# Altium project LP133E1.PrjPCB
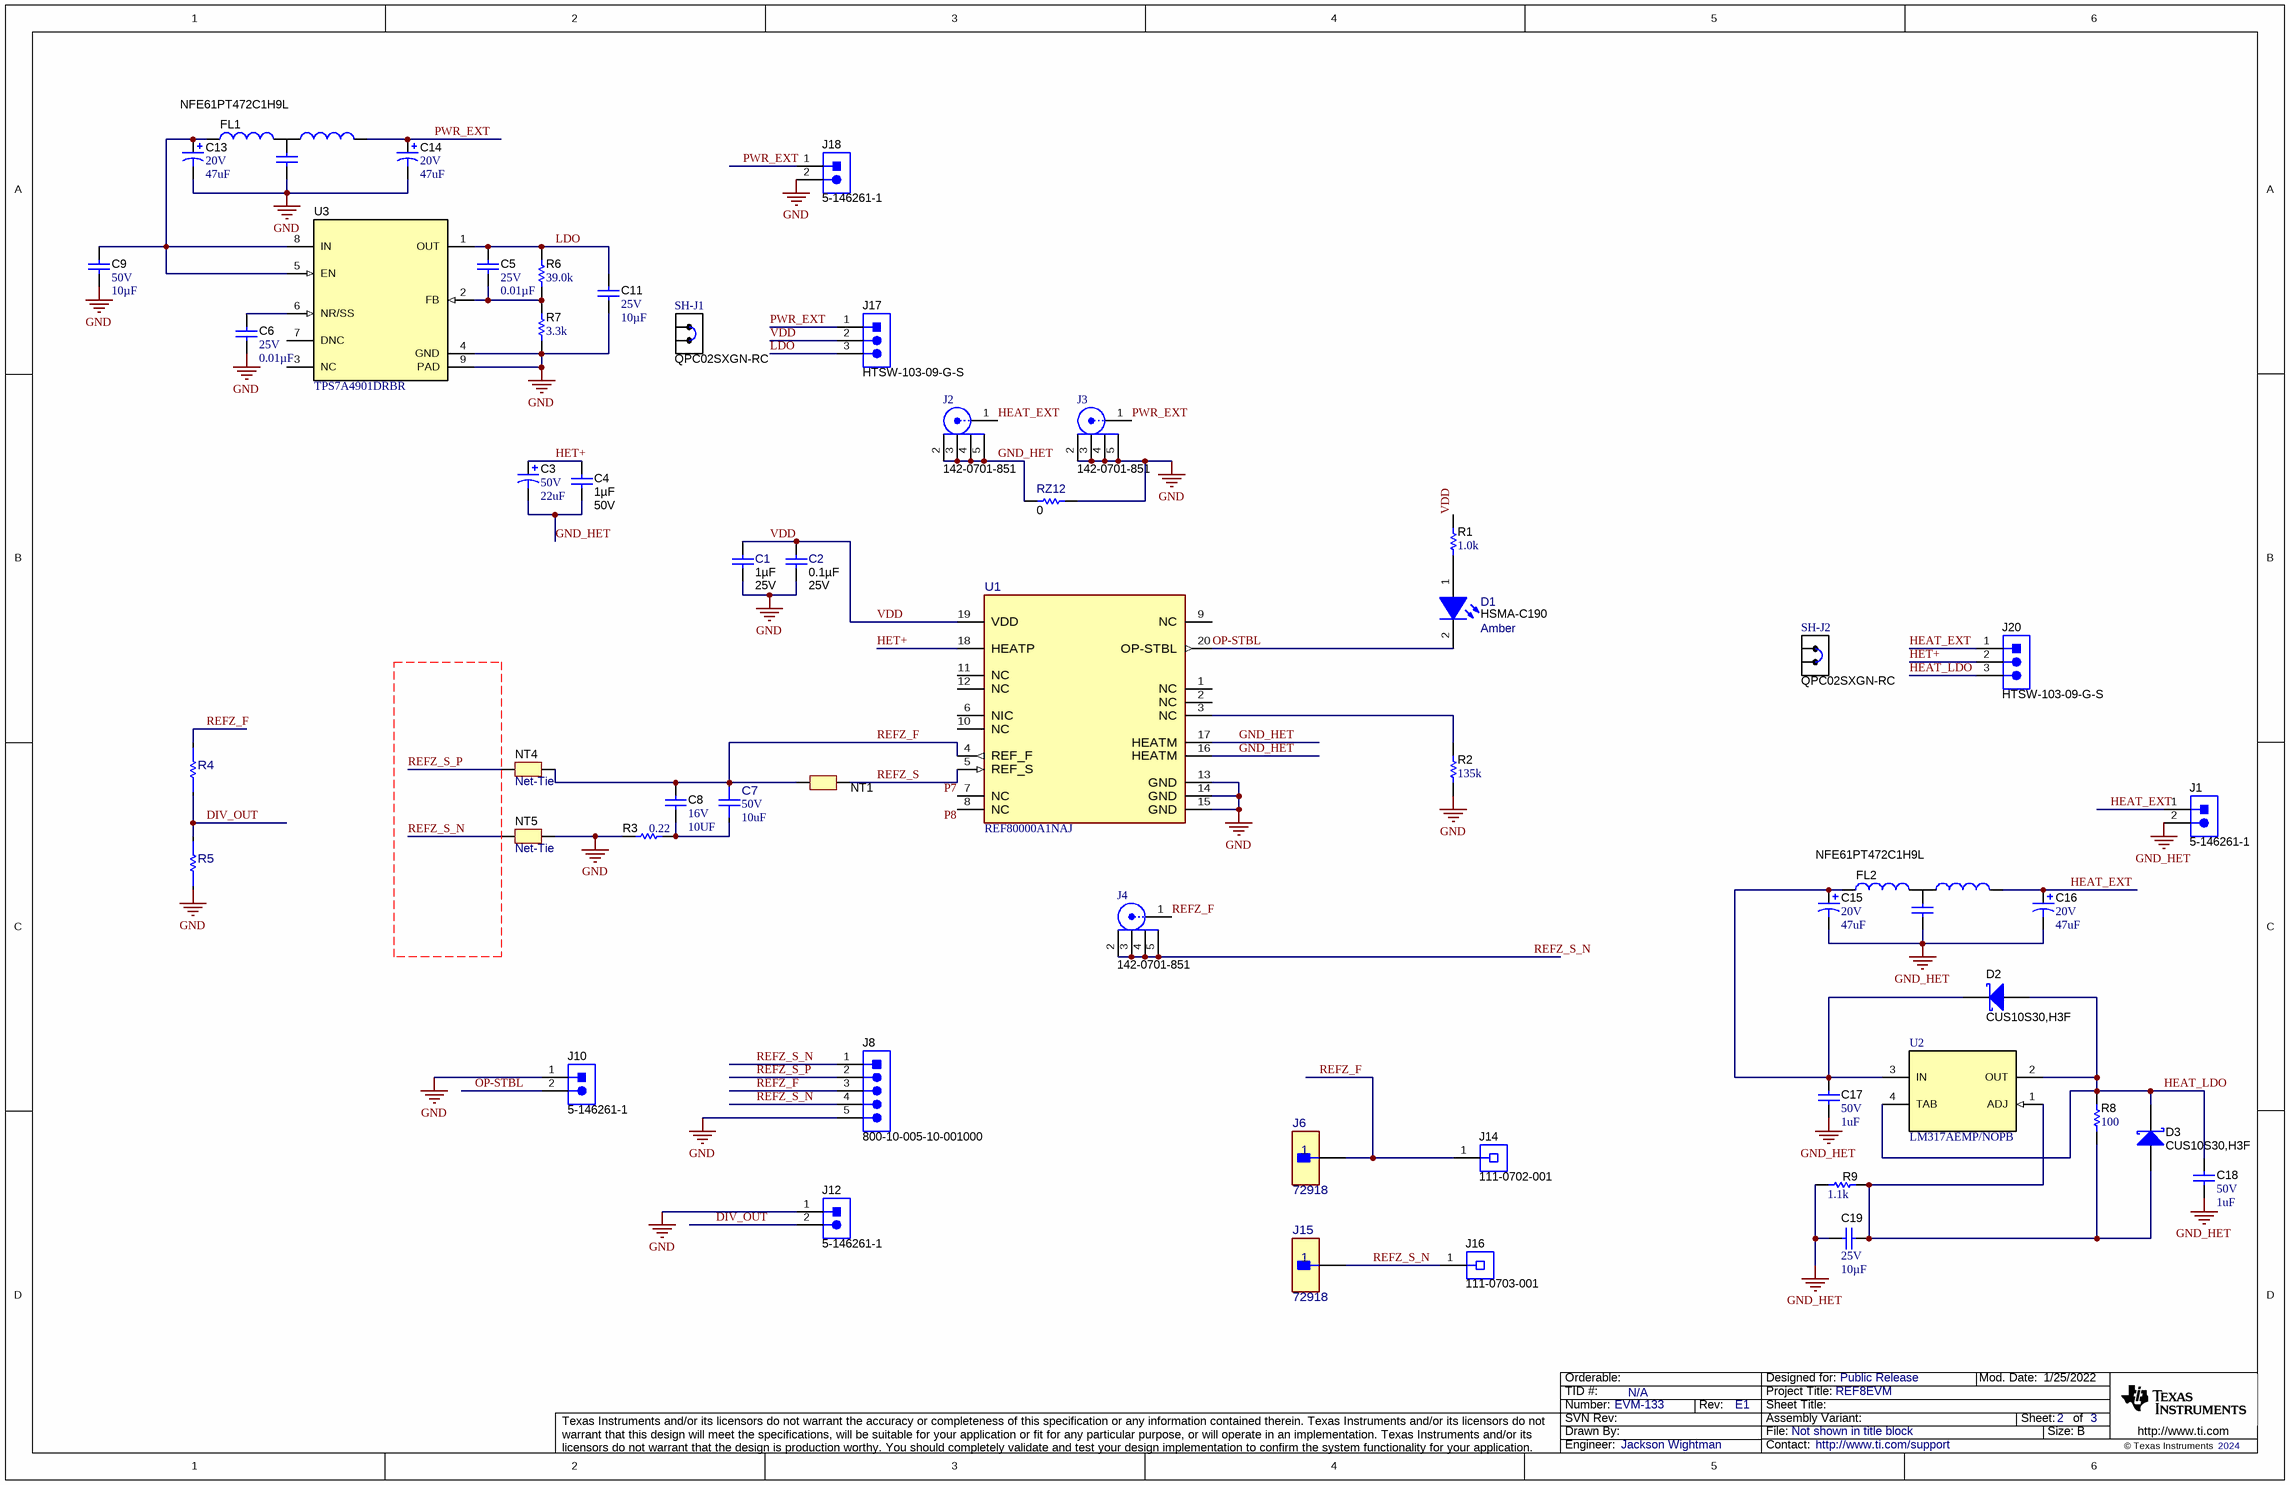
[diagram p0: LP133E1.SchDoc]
CopyrightYear: 2024; PCB_Layout: Jackson Wightman; PCB_Rev: E1; PRJ_Customer: Public Release; PRJ_Engineer: Jackson Wightman; PRJ_Number: EVM-133; PRJ_Title: REF8EVM; SCH_Rev: E1; TechSupport: http://www.ti.com/support; TID: N/A
2 sheets, 74 parts. Net scope: global (net labels, ports and power ports of the same name join across sheets).
Board file: LP133E1.PcbDoc
Sheets:
  LP133E1.SchDoc
  LP133E1_Hardware.SchDoc

## Sheet LP133E1.SchDoc
size 431 x 279 mm; Date: Not shown in title block; ApprovedBy: Not shown in title block; CheckedBy: Not shown in title block; Author: Not shown in title block; CompanyName: Not shown in title block; Engineer: Not shown in title block; Organization: Not shown in title block; Address1: Not shown in title block; Address2: Not shown in title block; Address3: Not shown in title block; Address4: Not shown in title block; DocumentNumber: 2; Revision: Use project parameter SCH_Rev; SheetNumber: 2; SheetTotal: 3; PageSetup: Record=PageOptions¦CenterHorizontal=True¦CenterVertical=True¦PrintScale=1.00¦XCorrection=1.00¦YCorrection=1.00¦PrintKind=0¦BorderSize=5000000¦LeftOffset=0¦BottomOffset=0¦Orientation=2¦PaperLength=1000¦PaperWidth=1000¦Scale=100¦PaperSource=15¦PrintQuality=600¦MediaType=1¦DitherType=10¦PaperKind=Letter¦PrintScaleMode=1

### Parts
C1  Cap_F: 1µF  VDC_V: 25V  [0603]  (hidden comment: GRJ188R71E105KE11D)
C2  ValueDisplayed: 0.1µF  VDC_V: 25V  [0603]  (hidden comment: CL10A104KA8NNNC)
C3  VDC_V: 50V  ValueDisplayed: 22uF  [7361-38]  (hidden comment: TAJV226K050RNJ)
C4  Cap_F: 1µF  VDC_V: 50V  [0805_HV]  (hidden comment: CL21B105KBFNFNE)
C5  VDC_V: 25V  ValueDisplayed: 0.01µF  [0603]  (hidden comment: C0603C103F3GACTU)
C6  VDC_V: 25V  ValueDisplayed: 0.01µF  [0603]  (hidden comment: C0603C103F3GACTU)
C7  VDC_V: 50V  ValueDisplayed: 10uF  [FP-MKS2B051001N00JSSD_RADIAL-MFG]  (hidden comment: MKS2B051001N00JSSD)
C8  VDC_V: 16V  ValueDisplayed: 10UF  [1812]  (hidden comment: 16MU106MC44532)
C9  VDC_V: 50V  ValueDisplayed: 10µF  [1210_270]  (hidden comment: CL32B106KBJNNWE)
C11  VDC_V: 25V  ValueDisplayed: 10µF  [0603]  (hidden comment: GRM188R61E106KA73D)
C13  VDC_V: 20V  ValueDisplayed: 47uF  [7343-20]  (hidden comment: 20TQC47MYF)
C14  VDC_V: 20V  ValueDisplayed: 47uF  [7343-20]  (hidden comment: 20TQC47MYF)
C15  VDC_V: 20V  ValueDisplayed: 47uF  [7343-20]  (hidden comment: 20TQC47MYF)
C16  VDC_V: 20V  ValueDisplayed: 47uF  [7343-20]  (hidden comment: 20TQC47MYF)
C17  VDC_V: 50V  ValueDisplayed: 1uF  [0805_HV]  (hidden comment: C2012X6S1H105K125AB)
C18  VDC_V: 50V  ValueDisplayed: 1uF  [0805_HV]  (hidden comment: C2012X6S1H105K125AB)
C19  VDC_V: 25V  ValueDisplayed: 10µF  [0603]  (hidden comment: GRM188R61E106KA73D)
D1  HSMA-C190  value Amber  [HSMx-C190_Amber]
D2  CUS10S30,H3F  [SOD-323]
D3  CUS10S30,H3F  [SOD-323]
FL1  NFE61PT472C1H9L  [2706]
FL2  NFE61PT472C1H9L  [2706]
J1  5-146261-1  [CONN_5-146261-1]
J2  142-0701-851  [Emerson_142-0701-851]
J3  142-0701-851  [Emerson_142-0701-851]
J4  142-0701-851  [Emerson_142-0701-851]
J6  72918  [FP-72918_CONNECTOR_BANANA_PLUG-MFG]
J8  800-10-005-10-001000  [Mill-Max_800-10-005-10-001000]
J10  5-146261-1  [CONN_5-146261-1]
J12  5-146261-1  [CONN_5-146261-1]
J14  111-0702-001  [Emerson_111-0702-001]
J15  72918  [FP-72918_CONNECTOR_BANANA_PLUG-MFG]
J16  111-0703-001  [Emerson_111-0703-001]
J17  HTSW-103-09-G-S  [Samtec_HTSW-103-09-x-S]
J18  5-146261-1  [CONN_5-146261-1]
J20  HTSW-103-09-G-S  [Samtec_HTSW-103-09-x-S]
NT1  Net-Tie  [Net-Tie_10mil]  (value not drawn)  (net tie, no BOM)
NT4  Net-Tie  [Net-Tie_10mil]  (net tie, no BOM)
NT5  Net-Tie  [Net-Tie_10mil]  (net tie, no BOM)
R1  ValueDisplayed: 1.0k  [0402]  (hidden comment: CRCW04021K00JNED)
R2  ValueDisplayed: 135k  [0603]  (hidden comment: RT0603DRE07135KL)
R3  ValueDisplayed: 0.22  [0603]  (hidden comment: ERJ-3RQFR22V)
R4  Y0062100K000T9L  [FP-Y0062100K000T9L_RADIAL-MFG]  (value not drawn)
R5  Y0062100K000T9L  [FP-Y0062100K000T9L_RADIAL-MFG]  (value not drawn)
R6  ValueDisplayed: 39.0k  [0603]  (hidden comment: RC0603FR-0739KL)
R7  ValueDisplayed: 3.3k  [0603]  (hidden comment: RC0603JR-073K3L)
R8  ValueDisplayed: 100  [1206]  (hidden comment: CRCW1206100RFKEA)
R9  ValueDisplayed: 1.1k  [1206]  (hidden comment: CRCW12061K10JNEA)
RZ12  ValueDisplayed: 0  [0805_HV]  (hidden comment: CRCW08050000Z0EA)
SH-J1  QPC02SXGN-RC  [FP-QPC02SXGN-RC_JUMPER-MFG]
SH-J2  QPC02SXGN-RC  [FP-QPC02SXGN-RC_JUMPER-MFG]
U1  REF80000A1NAJ  [NAJ0020A-IPC_C]
U2  LM317AEMP/NOPB  [DCY0004A_N]
U3  TPS7A4901DRBR  [DRB0008A]

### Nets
GND: C1.2 C2.2 C6.2 C9.2 C11.2 C13.2(-) C14.2(-) FL1.2 J3.2 J3.3 J3.4 J3.5 J8.5 J10.1 J12.1 J18.2 NT5.1 R2.1 R3.1 R5.1 R7.1 RZ12.1 U1.13(GND) U1.14(GND) U1.15(GND) U3.4(GND) U3.9(PAD)
GND_HET: C3.2(-) C4.2 C15.2(-) C16.2(-) C17.2 C18.2 C19.1 FL2.2 J1.2 J2.2 J2.3 J2.4 J2.5 R9.1 RZ12.2 U1.16(HEATM) U1.17(HEATM)
DIV_OUT: J12.2 R4.1 R5.2
HEAT_EXT: C16.1(+) FL2.3 J1.1 J2.1 J20.1
HEAT_LDO: C18.1 D2.2(A) D3.1(K) J20.3 R8.2 U2.2(OUT) U2.4(TAB)
HET+: C3.1(+) C4.1 J20.2 U1.18(HEATP)
LDO: C5.1 C11.1 J17.3 R6.2 U3.1(OUT)
OP-STBL: D1.2(K) J10.2 U1.20(OP-STBL)
PWR_EXT: C14.1(+) FL1.3 J3.1 J17.1 J18.1
REFZ_F: C7.1 C8.1 J4.1 J6.1 J8.3 J14.1 NT1.1 NT4.1 R4.2 U1.4(REF_F)
REFZ_S: NT1.2 U1.5(REF_S)
REFZ_S_N: J4.2 J4.3 J4.4 J4.5 J8.1 J8.4 J15.1 J16.1 NT5.2
REFZ_S_P: J8.2 NT4.2
VDD: C1.1 C2.1 J17.2 R1.2 U1.19(VDD)
NetC5_2: C5.2 R6.1 R7.2 U3.2(FB)
NetC6_1: C6.1 U3.6(NR/SS)
NetC7_2: C7.2 C8.2 R3.2
NetC9_1: C9.1 C13.1(+) FL1.1 U3.5(EN) U3.8(IN)
NetC15_1: C15.1(+) C17.1 D2.1(K) FL2.1 U2.3(IN)
NetC19_2: C19.2 D3.2(A) R8.1 R9.2 U2.1(ADJ)
NetD1_1: D1.1(A) R1.1
NetR2_2: R2.2 U1.3(NC)

Not connected (* = marked no-connect by the designer): U1 1(NC) 2(NC) 6(NIC) 7(NC) 8(NC) 9(NC) 10(NC) 11(NC) 12(NC); U3 3(NC) 7(DNC)

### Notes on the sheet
- Labels drawn without touching a wire or pin: P7, P8

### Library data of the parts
C1 = CMP-0079720-1: CAP, CERM, 1 µF, 25 V,+/- 10%, X7R, 0603; Manufacturer: MuRata; TaMin_C: -55°C; Polarized: N; SizeAreaWB_mm2: 4.68; U/M: EA; Value: 1uF; TaMax_C: 125°C; SizeZ_mm: 1; SizeX_mm: 1.6; SizeY_mm: 0.8; SizeArea_mm2: 1.28; AEC Category: Q200
C2 = CMP-0085577-2: CAP, CERM, 0.1 µF, 25 V,+/- 10%, X5R, 0603; Manufacturer: Samsung Electro-Mechanics; SizeZ_mm: 1; AEC Qualified: N; SizeY_mm: 0.8; Green_REACh: Incomplete; SizeArea_mm2: 1.28; Green_Lifecycle: Active; SizeX_mm: 1.6; AEC Category: Q200; TaMin_C: -55°C; SizeAreaWB_mm2: 4.68; Cap_F: 100nF; U/M: EA; TaMax_C: 85°C; Value: 0.1uF
C3 = CMP-0064995-1: CAP, TA, 22 uF, 50 V, +/- 10%, 0.6 ohm, SMD; Manufacturer: AVX; TaMin_C: -55°C; ESR_ohm: 0.6; Polarized: Y; Green_Lifecycle: Active; SizeAreaWB_mm2: 75.33; Green_REACh: Passed; Value1: 0.6 ohm; U/M: EA; Value: 22uF; TaMax_C: 125°C; SizeZ_mm: 3.8; SizeX_mm: 7.3; SizeY_mm: 6.1; SizeArea_mm2: 44.53; CompType: Capacitor; AEC Qualified: N; Cap_F: 22µF; IRMS_A: 645mA; AEC Category: Q200
C4 = CMP-0080611-1: CAP, CERM, 1 µF, 50 V,+/- 10%, X7R, 0805; Manufacturer: Samsung; TaMin_C: -55°C; Polarized: N; SizeAreaWB_mm2: 6.75; U/M: EA; Value: 1uF; TaMax_C: 125°C; SizeZ_mm: 1.45; SizeX_mm: 2; SizeY_mm: 1.25; Cap_Case: 0805; SizeArea_mm2: 2.5; AEC Category: Q200
C5 C6 = CMP-0079995-1: CAP, CERM, 0.01 µF, 25 V,+/- 1%, C0G/NP0, 0603; Manufacturer: Kemet; TaMin_C: -55°C; Polarized: N; Green_Lifecycle: Active; SizeAreaWB_mm2: 4.68; Green_REACh: Passed; U/M: EA; Value: 0.01uF; TaMax_C: 125°C; SizeZ_mm: 1; SizeX_mm: 1.6; SizeY_mm: 0.8; SizeArea_mm2: 1.28; Cap_F: 10nF; AEC Category: Q200
C7 = CMP-0096040-1: 10 µF Film Capacitor 30V 50V Polyester, Polyethylene Terephthalate (PET), Metallized Radial; Manufacturer: WIMA; SizeZ_mm: 16mm; AEC Grade: Grade 2; AEC Qualified: Yes; Tolerance_%: 5%; Cap_F: 10µF; Value: 10µF
C8 = CMP-0012475-2: CAP FILM 10UF 20% 16VDC 1812; Manufacturer: Rubycon; TaMin_C: -40°C; Polarized: N; SizeAreaWB_mm2: 14.7; Value1: Unknown; U/M: EA; TaMax_C: 85°C; SizeZ_mm: 1.35; SizeX_mm: 3.2; SizeY_mm: 2.5; SizeArea_mm2: 8; Cap_F: 10µF; AEC Category: Q200
C9 = CMP-0079201-1: CAP, CERM, 10 µF, 50 V,+/- 10%, X7R, 1210; Manufacturer: Samsung Electro-Mechanics; TaMin_C: -55°C; ESR_ohm: 5m; Polarized: N; SizeAreaWB_mm2: 14.7; Value1: 0.005 ohm; U/M: EA; Value: 10uF; TaMax_C: 125°C; SizeZ_mm: 2.7; SizeX_mm: 3.2; SizeY_mm: 2.5; Cap_Case: 1210; SizeArea_mm2: 8; AEC Category: Q200
C11 C19 = CMP-0860569-1: CAP, CERM, 10 µF, 25 V,+/- 10%, X5R, 0603; Manufacturer: MuRata; SizeZ_mm: 1; AEC Category: Q200; AEC Qualified: N; TaMin_C: -55°C; SizeY_mm: 0.8; SizeAreaWB_mm2: 4.68; SizeArea_mm2: 1.28; TaMax_C: 85°C; SizeX_mm: 1.6; Value: 10uF; U/M: EA
C13-C16 = CMP-0012618-4: CAP, Tantalum Polymer, 47 uF, 20 V, +/- 20%, 0.055 ohm, 7343-20 SMD; Manufacturer: Panasonic; TaMin_C: -55°C; ESR_ohm: 55m; Polarized: Y; SizeAreaWB_mm2: 58.59; Value: 47uF; TaMax_C: 105°C; SizeZ_mm: 2; SizeX_mm: 7.3; SizeY_mm: 4.3; SizeArea_mm2: 31.39; CompType: Capacitor; AEC Qualified: N; Cap_F: 47µF; IRMS_A: 1.45A; AEC Category: Q200
C17 C18 = CMP-0007855-1: CAP, CERM, 1 uF, 50 V, +/- 10%, X6S, 0805; Manufacturer: TDK; TaMin_C: -55°C; ESR_ohm: 8.782m; Polarized: N; SizeAreaWB_mm2: 6.75; Value1: 0.008782 ohm; U/M: EA; Value: 1uF; TaMax_C: 105°C; SizeZ_mm: 1.45; SizeX_mm: 2; SizeY_mm: 1.25; Cap_Case: 0805; SizeArea_mm2: 2.5; Cap_F: 1µF; IRMS_A: 2.2049A; AEC Category: Q200
D1 = CMP-0003041-3: LED, Amber, SMD; Manufacturer: Avago; SizeY_mm: 0.8; Vf_V: 1.9V; Value1: 0.06W; Ir_A: 100µA; Power_TotalModule: 60mW; SizeZ_mm: 0.9; SizeX_mm: 1.6; Tjmax_C: 95°C; SizeArea_mm2: 1.28; Vr_V: 5V; SizeAreaWB_mm2: 4.68; Angle: 170; Io_A: 20mA; Type: AlInGaP
D2 D3 = CMP-0028893-2: Diode, Schottky, 20 V, 1 A, SOD-323; Manufacturer: Toshiba; Io_A: 1A; AEC Qualified: N; SizeY_mm: 1.35; SizeAreaWB_mm2: 8.695; Green_REACh: Incomplete; Value2: 0.37V; Vf_V: 370mV; TJmax_C: 125°C; Green_Lifecycle: Not Set; SizeZ_mm: 1; SizeArea_mm2: 3.645; Vr_V: 20V; AEC Category: Q101; SizeX_mm: 2.7; Value: 20V
FL1 FL2 = CMP-0001717-2: Filter LC High freq 4700PF, 2706; Manufacturer: MuRata
J1 J10 J12 J18 = CMP-0054947-1: Header, 100mil, 2x1, Gold, TH; Manufacturer: TE Connectivity; CT: FALSE; Green_REACh: Passed; CNHeader: TRUE; Green_Lifecycle: Active
J2-J4 = CMP-0055822-3: Connector, End launch SMA, 50 ohm, SMT; Manufacturer: Cinch Connectivity; Green_Lifecycle: Not Set; Green_REACh: Incomplete
J6 J15 = CMP-0092456-1: Banana Plug Connector Standard Banana Threaded, External (Nut) -; Manufacturer: Pomona Electronics; Current_A: 36A; AEC Qualified: No; ContactFinish: Nickel
J8 = CMP-0055088-1: Header, 100mil, 5x1, TH; Manufacturer: Mill-Max; CT: FALSE; CNHeader: TRUE
J14 = CMP-0075036-1: Binding Post, Red, TH; Manufacturer: Cinch Connectivity; CT: False; CompType: Receptacle
J16 = CMP-0075035-1: Binding Post, Black, TH; Manufacturer: Cinch Connectivity; CT: False
J17 J20 = CMP-0075627-1: Header, 100mil, 3x1, Gold, TH; Manufacturer: Samtec; Pitch_mm: 2.54; Gender: Male; Cert_CSA: Y; CT: False; Row_Count: 1
NT1 NT4 NT5 = CMP-0078142-3: Single point connection between nets.
R1 = CMP-0026852-2: RES, 1.0 k, 5%, 0.063 W, 0402; Manufacturer: Vishay-Dale; Power_W: 63mW; TempCo: 200 ppm/C; Value_Code: 1k00; U/M: EA; Value: 1.0k; EIA_Code: E24; Res_ohm: 1k; SizeX_mm: 1; SizeY_mm: 0.5; SizeZ_mm: 0.6; Value2: 0.063W; VDC_V: 50V; AEC Category: Q200
R2 = CMP-0024657-2: RES, 135 k, 0.5%, 0.1 W, 0603; Manufacturer: Yageo America; Power_W: 100mW; TempCo: 50 ppm/C; U/M: EA; Value: 135k; EIA_Code: E192; SizeX_mm: 1.6; SizeY_mm: 0.8; SizeZ_mm: 1; Value2: 0.1W; SizeArea_mm2: 1.28; VDC_V: 75V; AEC Category: Q200
R3 = CMP-0022712-3: RES, 0.22, 1%, 0.1 W, AEC-Q200 Grade 0, 0603; Manufacturer: Panasonic; Power_W: 100mW; TempCo: 300 ppm/C; Value_Code: R220; Value: 0.22; EIA_Code: E96; SizeX_mm: 1.6; SizeY_mm: 0.8; SizeZ_mm: 1; Value2: 0.1W; SizeArea_mm2: 1.28; AEC Qualified: Y; AEC Category: Q200; AEC Grade: 0; SizeAreaWB_mm2: 4.68
R4 R5 = CMP-0096565-1: Res Metal Foil 100K Ohm 0.01% 3/5W ±1ppm/°C Molded RDL Thru-Hole Bulk; Manufacturer: Vishay Precision Group; Power_W: 600mW; Standoff Height: 0.254mm; AEC Qualified: No; SizeZ_mm: 8.53mm; VDC_V: 300V
R6 = CMP-0023073-5: RES, 39.0 k, 1%, 0.1 W, 0603; Manufacturer: Yageo; Power_W: 100mW; TempCo: 100 ppm/C; Value_Code: 39k0; Value: 39.0k; Res_ohm: 39k; SizeX_mm: 1.6; SizeY_mm: 0.8; SizeZ_mm: 1; Value2: 0.1W; SizeArea_mm2: 1.28; AEC Qualified: N; VDC_V: 75V; AEC Category: Q200; SizeAreaWB_mm2: 4.68
R7 = CMP-0025918-5: RES, 3.3 k, 5%, 0.1 W, 0603; Manufacturer: Yageo; Power_W: 100mW; TempCo: 100 ppm/C; Value_Code: 3k30; Value: 3.3k; EIA_Code: E24; SizeX_mm: 1.6; SizeY_mm: 0.8; SizeZ_mm: 1; Value2: 0.1W; SizeArea_mm2: 1.28; AEC Qualified: N; VDC_V: 75V; AEC Category: Q200; SizeAreaWB_mm2: 4.68
R8 = CMP-0016569-3: RES, 100, 1%, 0.25 W, AEC-Q200 Grade 0, 1206; Manufacturer: Vishay-Dale; Power_W: 250mW; TempCo: 100 ppm/C; Value_Code: 100R; Value: 100; EIA_Code: E96; SizeX_mm: 3.2; SizeY_mm: 1.6; SizeZ_mm: 1.35; Value2: 0.25W; SizeArea_mm2: 5.12; AEC Qualified: Y; VDC_V: 200V; AEC Category: Q200; AEC Grade: 0
R9 = CMP-0018604-3: RES, 1.1 k, 5%, 0.25 W, AEC-Q200 Grade 0, 1206; Manufacturer: Vishay-Dale; Power_W: 250mW; TempCo: 200 ppm/C; Value_Code: 1k10; Value: 1.1k; EIA_Code: E24; SizeX_mm: 3.2; SizeY_mm: 1.6; SizeZ_mm: 1.35; Value2: 0.25W; SizeArea_mm2: 5.12; AEC Qualified: Y; VDC_V: 200V; AEC Category: Q200; AEC Grade: 0
RZ12 = CMP-0020442-3: RES, 0, 5%, 0.125 W, AEC-Q200 Grade 0, 0805; Manufacturer: Vishay-Dale; Power_W: 125mW; TempCo: 200 ppm/C; Value_Code: 0000; Value: 0; EIA_Code: E24; SizeX_mm: 2; SizeY_mm: 1.25; SizeZ_mm: 1.45; Value2: 0.125W; SizeArea_mm2: 2.5; AEC Qualified: Y; VDC_V: 150V; AEC Category: Q200
SH-J1 SH-J2 = CMP-0087961-2: CONN JUMPER S2 (1 x 2) Position Shunt Connector Black Open Top 0.100" (2.54mm) GoldHORTING .100" GOLD; Manufacturer: Sullins; Current_A: 3A; Symbol Name: SYM-QPC02SXGN-RC
U1 = CMP-0120977-1: Temperature Compensated Buried Zener Reference With 0.1ppm/°C Drift and 1ppm Stability; Manufacturer: Texas Instruments; SizeZ_mm: 1.91mm; AEC Qualified: No; Max Supply Voltage: 16.5V; Min Supply Voltage: 10V; Nominal Supply Current: 15mA; Number Of Outputs: 1; Output Type: Fixed; Output Voltage: 7.6V; TaMax_C: +50°C; TaMin_C: +20°C
U2 = CMP-0070801-2: 3-Terminal Adjustable Regulator, 4-pin SOT-223, Pb-Free; Manufacturer: Texas Instruments; CompType: LDO IC; AEC Category: Q200; PackageTopMarking: XYTT*N07A; PowerWise: N
U3 = CMP-0073868-3: Vin 3V to 36V, 150mA, Ultra-Low-Noise, High-PSRR Low-Dropout (LDO) Linear Regulator, DRB0008A (VSON-8); Manufacturer: Texas Instruments; Alternate PartNumber: TPS7A4901DRBT; AEC Category: Q200; CompType: IC; SizeZ_mm: 1.0; Rating: Catalog; SizeAreaWB_mm2: 16.0; SizeX_mm: 3.0; SizeArea_mm2: 9.0; AEC Qualified: N

## Sheet LP133E1_Hardware.SchDoc
size 431 x 279 mm; Date: Not shown in title block; ApprovedBy: Not shown in title block; CheckedBy: Not shown in title block; Author: Not shown in title block; CompanyName: Not shown in title block; Engineer: Not shown in title block; Organization: Not shown in title block; Address1: Not shown in title block; Address2: Not shown in title block; Address3: Not shown in title block; Address4: Not shown in title block; DocumentNumber: 3; Revision: Use project parameter SCH_Rev; SheetNumber: 3; SheetTotal: 3; PageSetup: Record=PageOptions¦CenterHorizontal=True¦CenterVertical=True¦PrintScale=1.00¦XCorrection=1.00¦YCorrection=1.00¦PrintKind=0¦BorderSize=5000000¦LeftOffset=0¦BottomOffset=0¦Orientation=2¦PaperLength=1000¦PaperWidth=1000¦Scale=100¦PaperSource=15¦PrintQuality=600¦MediaType=1¦DitherType=10¦PaperKind=Letter¦PrintScaleMode=1
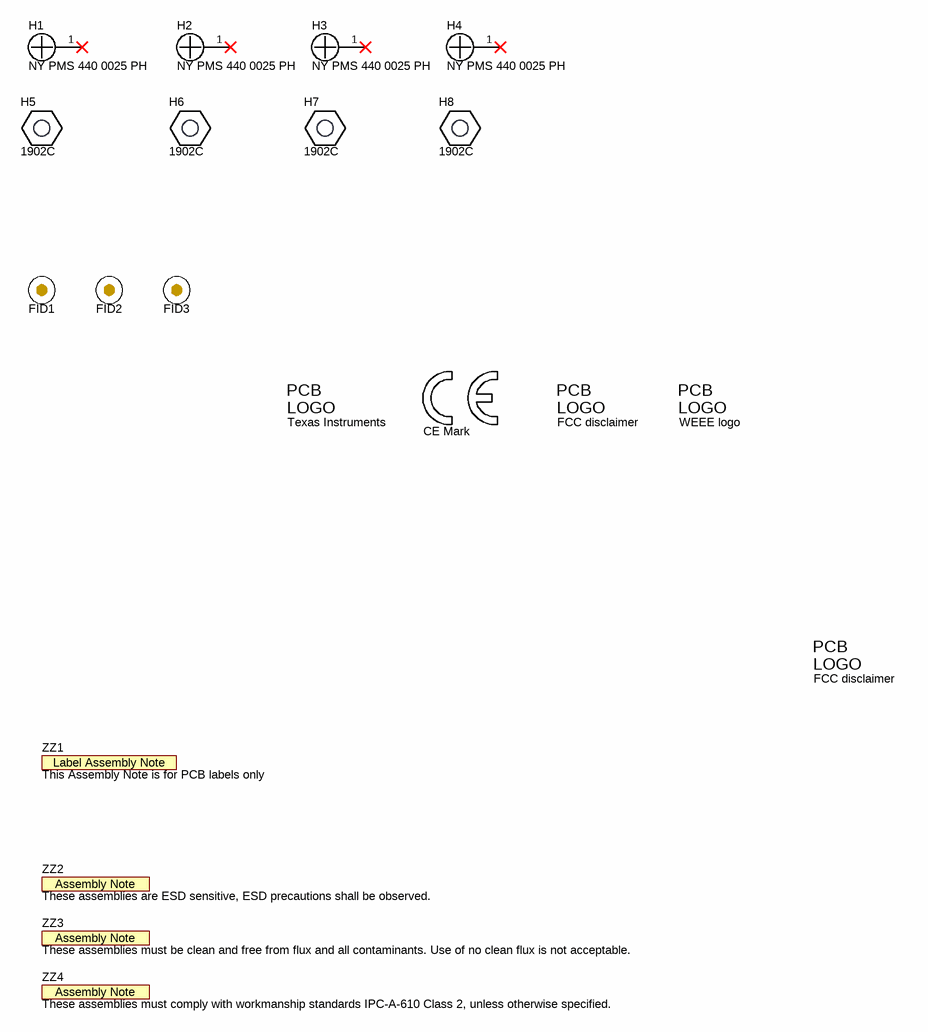
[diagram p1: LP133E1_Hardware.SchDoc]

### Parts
FID1  Fiducial  [Fiducial10-20]  (value not drawn)
FID2  Fiducial  [Fiducial10-20]  (value not drawn)
FID3  Fiducial  [Fiducial10-20]  (value not drawn)
H1  NY PMS 440 0025 PH  [NY PMS 440 0025 PH]
H2  NY PMS 440 0025 PH  [NY PMS 440 0025 PH]
H3  NY PMS 440 0025 PH  [NY PMS 440 0025 PH]
H4  NY PMS 440 0025 PH  [NY PMS 440 0025 PH]
H5  1902C  [Keystone_1902C]
H6  1902C  [Keystone_1902C]
H7  1902C  [Keystone_1902C]
H8  1902C  [Keystone_1902C]
Logo1  Texas Instruments  [TI_Stacked_Overlay_Small]  (no BOM)
Logo2  CE Mark  [CE_Mark_5mm]  (no BOM)
Logo3  FCC disclaimer  [FCC_disclaimer]  (no BOM)
Logo4  WEEE logo  [WEEE_Minimum]  (no BOM)
Logo5  FCC disclaimer  [FCC_disclaimer]  (no BOM)
ZZ1  This Assembly Note is for PCB labels only  [AssemblyNoteLabel]  (no BOM)
ZZ2  These assemblies are ESD sensitive, ESD precautions shall be observed.  [AssemblyNote]  (no BOM)
ZZ3  These assemblies must be clean and free from flux and all contaminants. Use of no clean flux is not acceptable.  [AssemblyNote]  (no BOM)
ZZ4  These assemblies must comply with workmanship standards IPC-A-610 Class 2, unless otherwise specified.  [AssemblyNote]  (no BOM)

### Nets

Not connected (* = marked no-connect by the designer): H1 1*; H2 1*; H3 1*; H4 1*

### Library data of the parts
FID1-FID3 = CMP-0077181-1: Fiducial mark.  There is nothing to buy or mount.
H1-H4 = CMP-0003617-1: Machine Screw, Round, #4-40 x 1/4, Nylon, Philips panhead; Manufacturer: B&F Fastener Supply; CompType: Hardware
H5-H8 = CMP-0003610-1: Standoff, Hex, 0.5"L #4-40 Nylon; Manufacturer: Keystone; CompType: Hardware
Logo1 = CMP-0074838-1: Texas Instrument Corporate Signature; SymbolCreator: a0412235; Lib Reference: TI_Logo; Library Reference: Logo
Logo2 = CMP-0074844-1: SymbolCreator: a0412235
Logo3 Logo5 = CMP-0074847-1: FCC_disclaimer; Library Reference: Logo
Logo4 = CMP-0074769-1
ZZ1 = CMP-0003616-3
ZZ2 = CMP-0077236-1
ZZ3 = CMP-0077237-1
ZZ4 = CMP-0077238-1

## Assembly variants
001: not fitted J14 J16 R2 R4 R5 RZ12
